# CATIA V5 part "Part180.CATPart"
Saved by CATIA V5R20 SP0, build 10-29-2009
Part number: IA 571720
Revision: ANY
Definition: UNKNOWN
Nomenclature: IA 571720
Source: Unknown
Bounding box of the stored display mesh (mm): x -3.35 to 3.35, y -7.95 to 9.02, z -3.186 to 3.186
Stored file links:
  C:\Users\Utente\Desktop\IO LAVORO\3D X SITO CF\CUMSA\3D files FA\FA 126712-20\Part180.CATPart

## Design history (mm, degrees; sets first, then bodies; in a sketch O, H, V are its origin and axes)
Body1 "Cortar-Extruir4" (main body)
  Solid1: solid without history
